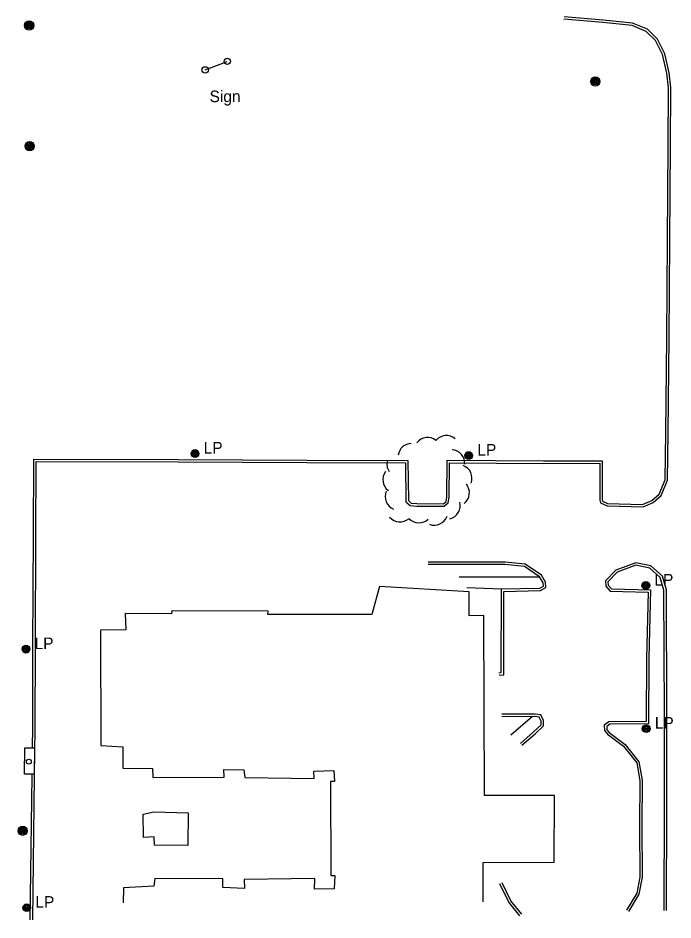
# Model space of a CAD drawing. Extents: x 2402803 to 2427059, y 6985292 to 6997652.
# Drawn here: x 2422162.8 to 2422433.9, y 6990850 to 6991223.7 of the extents above; entities that cross this region are included whole.
import ezdxf

# ---------------------------------------------------------------- set-up
doc = ezdxf.new("R2010")
doc.units = 0
for name, color, linetype in [('p_dtm sidewalk', 7, 'Continuous'), ('p_road - paved curb', 7, 'Continuous'), ('p_road bridge end', 7, 'Continuous'), ('p_structure building', 7, 'Continuous'), ('p_structure general', 7, 'Continuous'), ('p_structure sign', 7, 'Continuous'), ('p_utility manhole', 7, 'Continuous'), ('p_veg woods', 7, 'Continuous')]:
    doc.layers.add(name, color=color, linetype=linetype)

msp = doc.modelspace()

# ---------------------------------------------------------------- linework, layer by layer
at = {"layer": 'p_dtm sidewalk'}
for points in [[(2422378.79, 6990992.05), (2422345.36, 6990992.07)], [(2422362.93, 6990987.06), (2422348.63, 6990987.64)], [(2422375.83, 6990934.28), (2422366.77, 6990926.56)]]:
    msp.add_lwpolyline(points, dxfattribs=at)
at = {"layer": 'p_road - paved curb'}
for points in [[(2422168.75, 6990921.62), (2422168.85, 6990929.46), (2422168.97, 6990963.62), (2422169.14, 6991009.4), (2422169.29, 6991040.9), (2422229.15, 6991040.79), (2422282.3, 6991040.49), (2422324.24, 6991040.39), (2422324.4, 6991023.73), (2422325.57, 6991022.68), (2422327.9, 6991022.49), (2422338.89, 6991022.43), (2422339.99, 6991023.32), (2422340.27, 6991025.24), (2422340.51, 6991040.47), (2422380.38, 6991040.19), (2422404.7, 6991040.2), (2422404.7, 6991024.21), (2422404.81, 6991023.57), (2422406.89, 6991022.58), (2422421.39, 6991022.12), (2422425.15, 6991023.79), (2422428.19, 6991026.46), (2422430.71, 6991032.37), (2422430.99, 6991051.79), (2422431.39, 6991091.15), (2422431.62, 6991131.54), (2422431.97, 6991170.88), (2422432.13, 6991194.79), (2422431.35, 6991200.81), (2422429.66, 6991208.51), (2422426.78, 6991214.36), (2422422.82, 6991218.15), (2422417.01, 6991220.54), (2422404.96, 6991221.81), (2422388.8, 6991223.16)], [(2422168.87, 6990850.03), (2422169.59, 6990909.55), (2422169.85, 6990929.45), (2422169.97, 6990963.62), (2422170.14, 6991009.4), (2422170.29, 6991039.9), (2422229.15, 6991039.79), (2422282.3, 6991039.49), (2422323.25, 6991039.39), (2422323.4, 6991023.28), (2422325.15, 6991021.71), (2422327.86, 6991021.49), (2422339.24, 6991021.43), (2422340.92, 6991022.79), (2422341.27, 6991025.16), (2422341.49, 6991039.46), (2422380.38, 6991039.19), (2422403.7, 6991039.2), (2422403.7, 6991024.13), (2422403.91, 6991022.89), (2422406.65, 6991021.59), (2422421.59, 6991021.11), (2422425.7, 6991022.94), (2422429.02, 6991025.86), (2422431.71, 6991032.16), (2422431.99, 6991051.78), (2422432.39, 6991091.14), (2422432.62, 6991131.53), (2422432.97, 6991170.87), (2422433.13, 6991194.85), (2422432.34, 6991200.98), (2422430.61, 6991208.84), (2422427.6, 6991214.96), (2422423.37, 6991219), (2422417.26, 6991221.52), (2422405.05, 6991222.81), (2422388.88, 6991224.16)], [(2422361.92, 6990951.42), (2422363.88, 6990951.54), (2422363.93, 6990986.16), (2422379.04, 6990986.45), (2422381.33, 6990987.69), (2422381.14, 6990989.92), (2422379.49, 6990992.85), (2422372.78, 6990997.43), (2422364.42, 6990998.24), (2422332.66, 6990998.29)], [(2422361.86, 6990952.42), (2422362.88, 6990952.48), (2422362.93, 6990987.14), (2422378.78, 6990987.45), (2422380.28, 6990988.26), (2422380.16, 6990989.62), (2422378.73, 6990992.16), (2422372.43, 6990996.46), (2422364.37, 6990997.24), (2422332.66, 6990997.29)], [(2422431.32, 6990853.98), (2422431.39, 6990896.86), (2422431.46, 6990935.87), (2422431.21, 6990986.8), (2422429.58, 6990992.51), (2422424.79, 6990996.69), (2422418.53, 6990998.02), (2422410.24, 6990994.92), (2422405.98, 6990990.55), (2422406.11, 6990988.34), (2422407.99, 6990986.22), (2422423.61, 6990985.79), (2422422.93, 6990958.53), (2422422.87, 6990932.25), (2422407.41, 6990932.09), (2422405.52, 6990930.72), (2422405.65, 6990928.46), (2422406.78, 6990926.99), (2422413.49, 6990922.01), (2422418.94, 6990915.07), (2422420.16, 6990907.87), (2422420.09, 6990889), (2422420.24, 6990867.81), (2422418.92, 6990861.13), (2422414.67, 6990854.04)], [(2422430.32, 6990853.98), (2422430.39, 6990896.86), (2422430.46, 6990935.87), (2422430.21, 6990986.66), (2422428.7, 6990991.95), (2422424.33, 6990995.77), (2422418.61, 6990996.98), (2422410.8, 6990994.06), (2422407, 6990990.17), (2422407.09, 6990988.74), (2422408.45, 6990987.21), (2422424.63, 6990986.76), (2422423.93, 6990958.52), (2422423.87, 6990931.26), (2422407.74, 6990931.09), (2422406.55, 6990930.23), (2422406.63, 6990928.83), (2422407.49, 6990927.71), (2422414.19, 6990922.73), (2422419.88, 6990915.49), (2422421.16, 6990907.95), (2422421.09, 6990889), (2422421.24, 6990867.72), (2422419.87, 6990860.77), (2422415.53, 6990853.53)], [(2422371.43, 6990922.42), (2422376.87, 6990927.16), (2422380.34, 6990930.42), (2422380.32, 6990932.61), (2422379.17, 6990935.04), (2422376.89, 6990935.28), (2422363.07, 6990935.23)], [(2422370.77, 6990923.17), (2422376.2, 6990927.9), (2422379.34, 6990930.85), (2422379.32, 6990932.38), (2422378.51, 6990934.1), (2422376.84, 6990934.28), (2422363.07, 6990934.23)], [(2422167.87, 6990850.04), (2422168.59, 6990909.56), (2422168.6, 6990910.18)], [(2422370.55, 6990851.75), (2422366.02, 6990857.4), (2422362.32, 6990865.02)], [(2422371.33, 6990852.38), (2422366.87, 6990857.94), (2422363.22, 6990865.46)]]:
    msp.add_lwpolyline(points, dxfattribs=at)
at = {"layer": 'p_road bridge end'}
msp.add_lwpolyline([(2422169.64, 6990921.28), (2422169.5, 6990910.42), (2422165.5, 6990910.47), (2422165.64, 6990921.33)], close=True, dxfattribs=at)
at = {"layer": 'p_structure building'}
msp.add_lwpolyline([(2422355.35, 6990857.6), (2422355.42, 6990873.78), (2422384.75, 6990874.04), (2422384.86, 6990901.57), (2422355.86, 6990901.54), (2422355.7, 6990976.11), (2422349.63, 6990976.03), (2422349.62, 6990985.96), (2422312.43, 6990988.11), (2422309.23, 6990976.57), (2422266.22, 6990976.51), (2422266.34, 6990977.91), (2422226.41, 6990978.04), (2422226.39, 6990976.88), (2422207.15, 6990976.99), (2422207.4, 6990970.25), (2422196.88, 6990970.02), (2422197.05, 6990922.36), (2422206.18, 6990921.72), (2422206.24, 6990912.98), (2422218.47, 6990912.83), (2422218.62, 6990909.01), (2422248.13, 6990909.19), (2422248, 6990912.37), (2422256.34, 6990912.27), (2422256.67, 6990909.01), (2422285.46, 6990908.66), (2422285.25, 6990911.72), (2422293.55, 6990911.96), (2422293.84, 6990907.35), (2422292.11, 6990907.43), (2422292.23, 6990868.39), (2422293.99, 6990868.42), (2422293.74, 6990862.91), (2422285.57, 6990862.81), (2422285.6, 6990867.21), (2422256.39, 6990866.75), (2422256.48, 6990863.07), (2422247.64, 6990863.44), (2422247.61, 6990867.12), (2422219.37, 6990867.26), (2422218.94, 6990864.01), (2422206.39, 6990863.38), (2422206.34, 6990857.14)], dxfattribs=at)
msp.add_lwpolyline([(2422214.6, 6990893.81), (2422218.94, 6990894.83), (2422233.22, 6990894.44), (2422233.15, 6990880.9), (2422219.35, 6990881.05), (2422219.1, 6990884.53), (2422214.68, 6990884.25)], close=True, dxfattribs=at)
at = {"layer": 'p_structure general'}
msp.add_circle((2422167.24, 6990915.61), 1, dxfattribs=at)
at = {"layer": 'p_structure sign'}
msp.add_line((2422240.27, 6991202.18), (2422249.43, 6991205.71), dxfattribs=at)
for centre in [(2422249.44, 6991205.72), (2422240.28, 6991202.19)]:
    msp.add_circle(centre, 1.3, dxfattribs=at)
at = {"layer": 'p_utility manhole'}
for centre, radius in [((2422167.38, 6991220.59), 1.9), ((2422167.38, 6991220.59), 1.44), ((2422167.38, 6991220.59), 0.973), ((2422167.38, 6991220.59), 0.539), ((2422167.38, 6991220.59), 0.192), ((2422401.8, 6991197.39), 1.9), ((2422401.8, 6991197.39), 1.44), ((2422401.8, 6991197.39), 0.973), ((2422401.8, 6991197.39), 0.539), ((2422401.8, 6991197.39), 0.192), ((2422167.57, 6991170.57), 1.9), ((2422167.57, 6991170.57), 1.44), ((2422167.57, 6991170.57), 0.973), ((2422167.57, 6991170.57), 0.539), ((2422167.57, 6991170.57), 0.192), ((2422236.07, 6991043.25), 1.6), ((2422236.07, 6991043.25), 1.3), ((2422236.07, 6991043.25), 1), ((2422236.07, 6991043.25), 0.539), ((2422236.07, 6991043.25), 0.192), ((2422349.37, 6991042.42), 1.6), ((2422349.37, 6991042.42), 1.3), ((2422349.37, 6991042.42), 1), ((2422349.37, 6991042.42), 0.539), ((2422349.37, 6991042.42), 0.192), ((2422422.71, 6990988.58), 1.6), ((2422422.71, 6990988.58), 1.3), ((2422422.71, 6990988.58), 1), ((2422422.71, 6990988.58), 0.539), ((2422422.71, 6990988.58), 0.192), ((2422166.06, 6990962.22), 1.6), ((2422166.06, 6990962.22), 1.3), ((2422166.06, 6990962.22), 1), ((2422166.06, 6990962.22), 0.539), ((2422166.06, 6990962.22), 0.192), ((2422422.86, 6990929.28), 1.6), ((2422422.86, 6990929.28), 1.3), ((2422422.86, 6990929.28), 1), ((2422422.86, 6990929.28), 0.539), ((2422422.86, 6990929.28), 0.192), ((2422164.69, 6990886.98), 1.9), ((2422164.69, 6990886.98), 1.44), ((2422164.69, 6990886.98), 0.973), ((2422164.69, 6990886.98), 0.539), ((2422164.69, 6990886.98), 0.192), ((2422166.39, 6990855.09), 1.6), ((2422166.39, 6990855.09), 1.3), ((2422166.39, 6990855.09), 1), ((2422166.39, 6990855.09), 0.539), ((2422166.39, 6990855.09), 0.192)]:
    msp.add_circle(centre, radius, dxfattribs=at)
at = {"layer": 'p_veg woods'}
for centre, start, end in [((2422340.16, 6991045.07), 50.0552, 140.0552), ((2422325.73, 6991041.73), 91.4058, 171.1457), ((2422332.33, 6991044.26), 51.8515, 141.8515), ((2422342.09, 6991039.18), 356.0794, 86.0794), ((2422321.14, 6991038.92), 164.733, 213.1923), ((2422319.49, 6991032.4), 143.1773, 233.1773), ((2422345.09, 6991033.03), 339.2646, 69.2646), ((2422344.02, 6991027.06), 308.0867, 38.0867), ((2422320.46, 6991025.38), 156.7797, 246.7797), ((2422340.22, 6991021.71), 284.2994, 14.2994), ((2422335.13, 6991019.23), 249.6319, 339.6319), ((2422320.97, 6991020.57), 220.0308, 310.0308), ((2422328.77, 6991020.2), 222.79, 312.79)]:
    msp.add_arc(centre, 5.65, start, end, dxfattribs=at)

# ---------------------------------------------------------------- texts
at = {"layer": 'p_structure sign'}
msp.add_text('Sign', height=4.8, dxfattribs=at).set_placement((2422242.08, 6991188.81))
at = {"layer": 'p_utility manhole'}
for p in [(2422236.07, 6991043.25), (2422349.37, 6991042.42), (2422422.71, 6990988.58), (2422166.06, 6990962.22), (2422422.86, 6990929.28), (2422166.39, 6990855.09)]:
    msp.add_text('  LP', height=4.8, dxfattribs=at).set_placement(p)

doc.saveas('drawing.dxf')
